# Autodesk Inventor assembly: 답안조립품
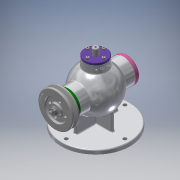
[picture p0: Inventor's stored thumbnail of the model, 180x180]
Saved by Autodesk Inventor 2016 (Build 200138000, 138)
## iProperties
Created: 2020-08
Part Number: 답안조립품
Material: 일반
Document SubType Name: Weldment
Designer: Administrator
Weld Material: Welded Aluminum-6061
Author: Administrator
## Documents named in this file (18)
- C:\Users\Administrator\Desktop\700806V1013\답안조립품.iam
- C:\Users\Administrator\Desktop\700806V1013\본체.ipt
- C:\Users\Administrator\Desktop\700806V1013\뒤커버.ipt
- C:\Users\Administrator\Desktop\700806V1013\앞커버.ipt
- C:\Users\Administrator\Desktop\700806V1013\베어링 6202.ipt
- 베어링 6202.ipt
- C:\Users\Administrator\Desktop\700806V1013\칼라.ipt
- C:\Users\Administrator\Desktop\700806V1013\편심축.ipt
- C:\Users\Administrator\Desktop\700806V1013\멈춤링 15x1.ipt
- C:\Users\Administrator\Desktop\700806V1013\멈춤링 35x1.6.ipt
- 멈춤링 35x1.6.ipt
- C:\Users\Administrator\Desktop\700806V1013\상부커버.ipt
- C:\Users\Administrator\Desktop\700806V1013\볼트 M4.ipt
- C:\Users\Administrator\Desktop\700806V1013\오일 실 15 30 7.ipt
- C:\Users\Administrator\Desktop\700806V1013\슬라이드.ipt
- C:\Users\Administrator\Desktop\700806V1013\키 3x3x12.ipt
- C:\Users\Administrator\Desktop\700806V1013\V-벨트풀리.ipt
- C:\Users\Administrator\Desktop\700806V1013\너트 M8.ipt
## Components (1 placed, 1 different names)
1. V-벨트풀리:1
